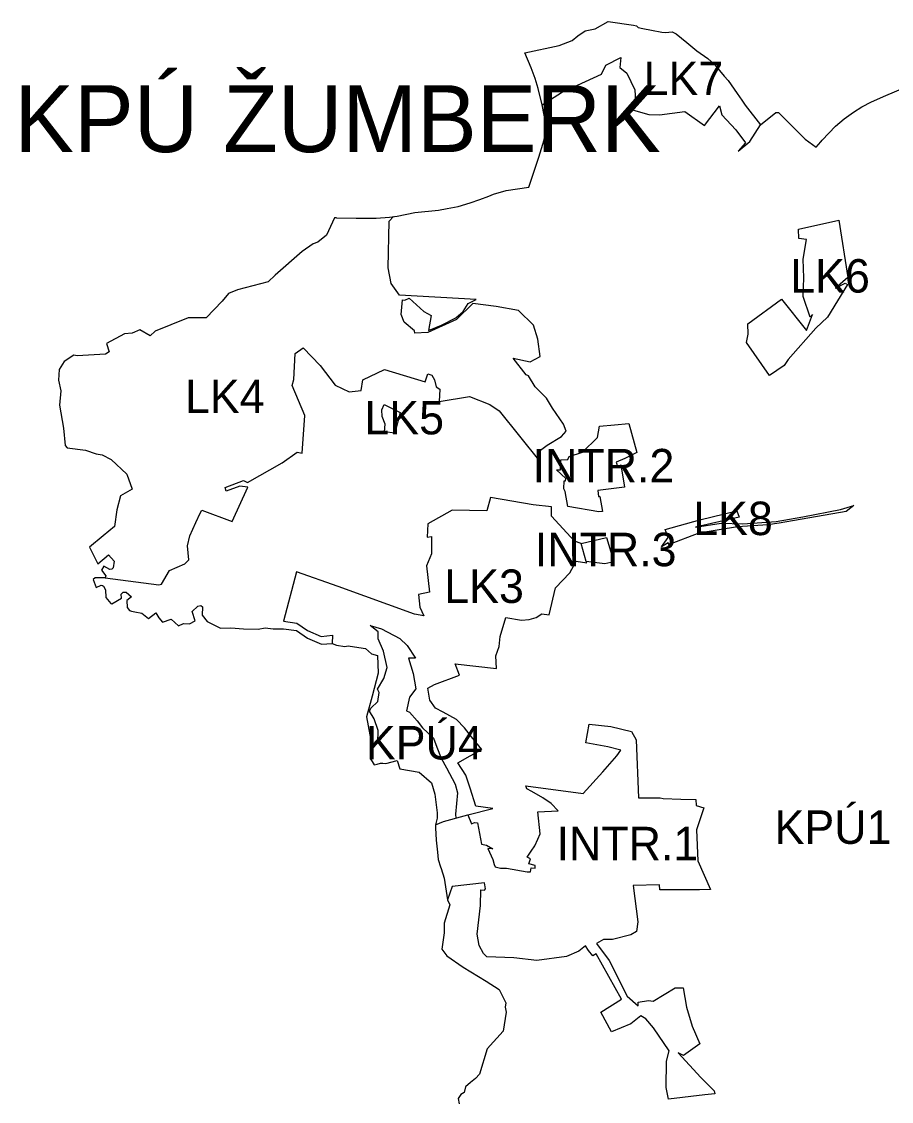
# Model space of a CAD drawing. Extents: x -744334 to -741989, y -1190045 to -1186328.
# Drawn here: x -744334 to -742775, y -1188264 to -1186328 of the extents above; entities that cross this region are included whole.
import ezdxf

# ---------------------------------------------------------------- set-up
doc = ezdxf.new("R2010")
doc.units = 0
for name, color, linetype in [('Hranice parcel', 7, 'Continuous'), ('Parcelní čísla', 7, 'Continuous'), ('Vnitřní kresba', 7, 'Continuous'), ('Značky budov', 7, 'Continuous')]:
    doc.layers.add(name, color=color, linetype=linetype)

msp = doc.modelspace()

# ---------------------------------------------------------------- linework, layer by layer
at = {"layer": 'Hranice parcel'}
msp.add_line((-743400.9, -1186477.3), (-743366.4, -1186455.4), dxfattribs=at)
for points in [[(-743366.4, -1186455.4), (-743294.4, -1186422.3), (-743286.6, -1186406.4), (-743259.8, -1186392.9), (-743261.7, -1186410.7), (-743248.9, -1186420.8), (-743234.9, -1186450.7), (-743233.5, -1186471.5), (-743237.3, -1186486.9), (-743209.9, -1186494.8), (-743190.7, -1186495.5), (-743145.5, -1186489.5), (-743109.8, -1186514.8), (-743083, -1186479.6), (-743079.1, -1186495.3), (-743054, -1186522.6), (-743036.7, -1186545.8), (-743049.3, -1186560.5), (-743028.9, -1186543), (-743009.5, -1186513.3)], [(-743867.4, -1187119.1), (-743840.2, -1187100), (-743831, -1187101.7), (-743826.3, -1187034.4), (-743849.4, -1186980.9), (-743846, -1186969.7), (-743844, -1186923.4), (-743829.7, -1186913.2), (-743798.7, -1186944.5), (-743771.8, -1186980.2), (-743747, -1186992.1), (-743725.6, -1186989.8), (-743722.5, -1186970.4), (-743683.7, -1186952), (-743610.6, -1186973.8), (-743605.8, -1186959.8), (-743598.7, -1186961.9), (-743593.9, -1186970.4), (-743591.2, -1186983.3), (-743584.7, -1186987), (-743585.4, -1187009.5), (-743531, -1187000.3), (-743494.6, -1187014.6), (-743478.2, -1187026.2), (-743405.1, -1187117.1), (-743408.5, -1187100.4), (-743392.2, -1187087.8), (-743366.3, -1187072.1), (-743357.8, -1187062.6), (-743362.9, -1187049.7), (-743382.3, -1187021.4), (-743393.5, -1187003.4), (-743413.3, -1186983.3), (-743425.5, -1186963.2), (-743429.6, -1186961.5), (-743452.7, -1186931.6), (-743422.5, -1186938.4), (-743404.8, -1186928.8), (-743408.5, -1186897.5), (-743416.3, -1186872.3), (-743443.5, -1186846.1), (-743483.7, -1186839), (-743525.5, -1186833.9), (-743554.8, -1186862.5), (-743605.8, -1186885.6), (-743629, -1186887), (-743629.6, -1186882.9), (-743648.3, -1186867.2), (-743653.8, -1186853.6), (-743651.1, -1186827.1), (-743647, -1186827.4), (-743639.5, -1186824.3), (-743613.3, -1186848.2), (-743599.7, -1186855.3), (-743604.8, -1186882.2), (-743581.7, -1186872.3), (-743555.8, -1186859.1), (-743542.9, -1186847.8), (-743533.4, -1186833.9), (-743519.4, -1186826.4), (-743656.5, -1186818.6), (-743671.6, -1186797.8), (-743677.2, -1186770), (-743675.1, -1186686.2), (-743667.7, -1186677.9)], [(-744011.3, -1187204.2), (-743956.9, -1187224.6), (-743928.7, -1187162.7), (-743943, -1187161), (-743967.5, -1187170.2), (-743969.2, -1187163.7), (-743936.5, -1187151.1), (-743929.3, -1187154.5), (-743867.4, -1187119.1)], [(-743330.9, -1187263.8), (-743343.2, -1187259.8), (-743384, -1187214.7), (-743384.3, -1187198), (-743417, -1187194.3), (-743493.9, -1187181.6), (-743500.1, -1187205.4), (-743562.2, -1187204.2), (-743605.7, -1187228.6), (-743606.9, -1187252.3), (-743599.2, -1187251.1), (-743599.2, -1187282.6), (-743608.5, -1187303.9), (-743602.9, -1187350.9), (-743622.4, -1187355.2), (-743620.5, -1187377.8), (-743613.4, -1187393.5), (-743629.8, -1187390.4)], [(-744184.6, -1187325.6), (-744088.2, -1187338), (-744083.5, -1187336.6), (-744069.2, -1187312.1), (-744055.2, -1187306.3), (-744041.6, -1187300.5), (-744034.5, -1187293), (-744036.9, -1187267.9), (-744032.4, -1187249.8), (-744021.9, -1187226.3), (-744014.4, -1187209.3), (-744011.3, -1187204.2)], [(-743606.2, -1187523.1), (-743594.3, -1187516.5), (-743549.2, -1187499.8), (-743556.9, -1187479.7), (-743483.1, -1187487.8), (-743484, -1187465.2), (-743477.9, -1187448.2), (-743476, -1187430.3), (-743466.1, -1187396.3), (-743438.3, -1187401), (-743424.1, -1187400), (-743411.8, -1187396.6), (-743401.3, -1187389.8), (-743388.6, -1187391.4), (-743376.9, -1187343.2), (-743351.6, -1187316.3), (-743340.1, -1187295.6), (-743321, -1187298.7), (-743322.2, -1187296.3)], [(-743629.8, -1187390.4), (-743766.8, -1187340.8), (-743841.5, -1187314.6), (-743864.8, -1187402.9)], [(-743864.8, -1187402.9), (-743840.7, -1187406.8), (-743821.7, -1187419.9), (-743797, -1187430.8), (-743777, -1187428.2), (-743777.3, -1187443)], [(-743705.5, -1187631.7), (-743695.5, -1187621.3), (-743694.9, -1187599.1), (-743702, -1187578.1), (-743710.4, -1187564.2), (-743707.9, -1187559.2), (-743695.5, -1187546.9), (-743693.1, -1187530.8), (-743696.2, -1187524.7), (-743684.8, -1187505.8), (-743678.6, -1187486.1), (-743685.4, -1187457.1), (-743695.2, -1187434.9), (-743695.2, -1187421.9), (-743709.1, -1187410.5), (-743689.1, -1187417), (-743656.4, -1187434.2), (-743643.1, -1187446.6), (-743628, -1187469.1), (-743640.9, -1187469.4), (-743632, -1187496.9), (-743627.7, -1187524.4), (-743639.1, -1187539.5), (-743644.3, -1187563.9), (-743639.1, -1187566.3), (-743624.9, -1187581.5), (-743615.6, -1187594.1), (-743595.6, -1187612.9), (-743589.7, -1187629), (-743582.3, -1187648.4), (-743572.5, -1187665.7), (-743557, -1187695), (-743553, -1187710.8), (-743556.4, -1187749.1), (-743556, -1187756.2)], [(-743534.1, -1187750), (-743489.5, -1187739.1), (-743520.2, -1187734.4), (-743529.8, -1187702.2), (-743537.8, -1187679.2), (-743552.2, -1187657.1), (-743529.8, -1187644.2), (-743509, -1187633.2), (-743527.7, -1187610.1), (-743540.4, -1187594.4), (-743554.3, -1187579.1), (-743578.5, -1187566.4), (-743592, -1187559), (-743602.2, -1187544.5), (-743606.2, -1187523.1)]]:
    msp.add_lwpolyline(points, dxfattribs=at)
for points in [[(-742869.2, -1186684.4), (-742853, -1186787), (-742875.3, -1186806.1), (-742857.9, -1186797.1), (-742853.8, -1186799.6), (-742889.5, -1186858.4), (-742910.6, -1186877.8), (-742960, -1186933.8), (-742967.3, -1186944.7), (-742993.2, -1186962.6), (-743034.6, -1186903.8), (-743031.7, -1186888.8), (-743032.1, -1186870.1), (-742972.2, -1186825.9), (-742927.2, -1186882.3), (-742916.3, -1186853.5), (-742920.3, -1186858), (-742933.3, -1186821.1), (-742932.1, -1186787.8), (-742933.3, -1186754.2), (-742927.2, -1186718.9), (-742941, -1186716.9), (-742941.4, -1186700.2)], [(-743655.6, -1187029.2), (-743665.1, -1187066), (-743683.5, -1187063.4), (-743682.2, -1187050), (-743688.1, -1187036), (-743688.3, -1187024.5), (-743684.2, -1187014.8)], [(-743180.4, -1187238.7), (-743118.5, -1187221.5), (-743051.9, -1187205.4), (-743047.7, -1187216.8), (-743126.3, -1187234.8), (-743080, -1187227.5), (-743041.5, -1187228.3), (-742981.7, -1187224.1), (-742933.8, -1187216.3), (-742866.2, -1187202.8), (-742842.2, -1187195.8), (-742856, -1187206.7), (-742975.9, -1187227.3), (-742996.7, -1187230.4), (-743050.6, -1187234), (-743120.3, -1187245.2), (-743173.4, -1187265.5), (-743175.3, -1187262.8), (-743186.9, -1187269.6), (-743175.2, -1187252.9)]]:
    msp.add_lwpolyline(points, close=True, dxfattribs=at)
at = {"layer": 'Parcelní čísla'}
for p, q in [((-743337.2, -1186353.8), (-743323.8, -1186344.8)), ((-743323.8, -1186344.8), (-743306.1, -1186341.6)), ((-743306.1, -1186341.6), (-743282.4, -1186328.4)), ((-743282.4, -1186328.4), (-743237.2, -1186334.6)), ((-743237.2, -1186334.6), (-743232.1, -1186336.2)), ((-743232.1, -1186336.2), (-743228.6, -1186338.7)), ((-743228.6, -1186338.7), (-743220.8, -1186340.9)), ((-743220.8, -1186340.9), (-743204.8, -1186343.9)), ((-743204.8, -1186343.9), (-743186.3, -1186347.3)), ((-743370.6, -1186371.1), (-743347.3, -1186362.5)), ((-743347.3, -1186362.5), (-743337.2, -1186353.8)), ((-743186.3, -1186347.3), (-743179.9, -1186347.7)), ((-743179.9, -1186347.7), (-743167.8, -1186346.8)), ((-743167.8, -1186346.8), (-743160.6, -1186350.3)), ((-743160.6, -1186350.3), (-743141.7, -1186365.6)), ((-743432.2, -1186384.6), (-743370.6, -1186371.1)), ((-743141.7, -1186365.6), (-743123.4, -1186380.8)), ((-743123.4, -1186380.8), (-743104.2, -1186394.4)), ((-743420.5, -1186411), (-743432.2, -1186384.6)), ((-743104.2, -1186394.4), (-743091.7, -1186406.1)), ((-743413.8, -1186430.3), (-743420.5, -1186411)), ((-743091.7, -1186406.1), (-743074.6, -1186426)), ((-743408, -1186448.5), (-743413.8, -1186430.3)), ((-743074.6, -1186426), (-743067.6, -1186434.2)), ((-743067.6, -1186434.2), (-743051.2, -1186457.4)), ((-743400.9, -1186477.3), (-743408, -1186448.5)), ((-743051.2, -1186457.4), (-743043.1, -1186469.4)), ((-742810.5, -1186472), (-742784.7, -1186460.7)), ((-742784.7, -1186460.7), (-742749.7, -1186445.8)), ((-743397.4, -1186495.9), (-743400.9, -1186477.3)), ((-743043.1, -1186469.4), (-743036.9, -1186478.1)), ((-743036.9, -1186478.1), (-743009.5, -1186513.3)), ((-742827.8, -1186481.3), (-742810.5, -1186472)), ((-743395.2, -1186510.1), (-743397.4, -1186495.9)), ((-743009.5, -1186513.3), (-742982.2, -1186491.2)), ((-742982.2, -1186491.2), (-742977.4, -1186491.2)), ((-742977.4, -1186491.2), (-742949.4, -1186519.5)), ((-742859.6, -1186502.8), (-742842.9, -1186490.9)), ((-742842.9, -1186490.9), (-742827.8, -1186481.3)), ((-743394.4, -1186521), (-743395.2, -1186510.1)), ((-742898.8, -1186541), (-742874.8, -1186515.5)), ((-742874.8, -1186515.5), (-742859.6, -1186502.8)), ((-743397.4, -1186540), (-743394.4, -1186521)), ((-742949.4, -1186519.5), (-742929.7, -1186538.8)), ((-743406.7, -1186571.2), (-743397.4, -1186540)), ((-742929.7, -1186538.8), (-742910, -1186553.7)), ((-742910, -1186553.7), (-742901.3, -1186543.7)), ((-742901.3, -1186543.7), (-742898.8, -1186541)), ((-743424.8, -1186625.1), (-743406.7, -1186571.2)), ((-743488.3, -1186637.7), (-743465.4, -1186630.9)), ((-743465.4, -1186630.9), (-743424.8, -1186625.1)), ((-743551.5, -1186660), (-743530.2, -1186653.4)), ((-743530.2, -1186653.4), (-743512.5, -1186647.5)), ((-743512.5, -1186647.5), (-743496.5, -1186641)), ((-743496.5, -1186641), (-743488.3, -1186637.7)), ((-743660.9, -1186677.2), (-743629.5, -1186670.8)), ((-743629.5, -1186670.8), (-743586.7, -1186666.2)), ((-743586.7, -1186666.2), (-743571.4, -1186663.2)), ((-743571.4, -1186663.2), (-743551.5, -1186660)), ((-743773.2, -1186680.1), (-743787.7, -1186711.1)), ((-743769.7, -1186680), (-743773.2, -1186680.1)), ((-743769.7, -1186680), (-743734.5, -1186680.9)), ((-743734.5, -1186680.9), (-743698.8, -1186680.9)), ((-743698.8, -1186680.9), (-743674.5, -1186678.6)), ((-743674.5, -1186678.6), (-743660.9, -1186677.2)), ((-743787.7, -1186711.1), (-743803.2, -1186723.9)), ((-743811.3, -1186726.6), (-743831.4, -1186740.7)), ((-743803.2, -1186723.9), (-743811.3, -1186726.6)), ((-743831.4, -1186740.7), (-743879.6, -1186782.6)), ((-743879.6, -1186782.6), (-743892.3, -1186794.8)), ((-743947.3, -1186809.1), (-743963.5, -1186815.8)), ((-743892.3, -1186794.8), (-743947.3, -1186809.1)), ((-743963.5, -1186815.8), (-743974.5, -1186829.5)), ((-743974.5, -1186829.5), (-744003.5, -1186859.6)), ((-744035.9, -1186859.3), (-744066.5, -1186872)), ((-744003.5, -1186859.6), (-744035.9, -1186859.3)), ((-744122, -1186880.9), (-744135.8, -1186886.9)), ((-744103.7, -1186891.4), (-744122, -1186880.9)), ((-744094.6, -1186883), (-744103.7, -1186891.4)), ((-744066.5, -1186872), (-744094.6, -1186883)), ((-744149.6, -1186887.9), (-744181.9, -1186905.5)), ((-744181.9, -1186905.5), (-744177.4, -1186920.5)), ((-744135.8, -1186886.9), (-744149.6, -1186887.9)), ((-744183.8, -1186924.2), (-744234.7, -1186927.3)), ((-744177.4, -1186920.5), (-744183.8, -1186924.2)), ((-744258, -1186937.7), (-744267, -1186952)), ((-744240.5, -1186926.3), (-744258, -1186937.7)), ((-744234.7, -1186927.3), (-744240.5, -1186926.3)), ((-744267, -1186952), (-744268, -1186970.9)), ((-744268, -1186970.9), (-744263.7, -1186990.2)), ((-744263.7, -1186990.2), (-744266.2, -1187015.9)), ((-744266.2, -1187015.9), (-744258.9, -1187056.9)), ((-744258.9, -1187056.9), (-744255.9, -1187088.1)), ((-744255.9, -1187088.1), (-744252.7, -1187092.5)), ((-744252.7, -1187092.5), (-744219.9, -1187096.7)), ((-744219.9, -1187096.7), (-744200.5, -1187103.2)), ((-744200.5, -1187103.2), (-744189.8, -1187105.1)), ((-744189.8, -1187105.1), (-744173.9, -1187113.1)), ((-744173.9, -1187113.1), (-744145.4, -1187139.6)), ((-744145.4, -1187139.6), (-744135.9, -1187166.5)), ((-744135.9, -1187166.5), (-744157.1, -1187178.5)), ((-744157.1, -1187178.5), (-744163.5, -1187203.3)), ((-744163.5, -1187203.3), (-744167.7, -1187233.4)), ((-744167.7, -1187233.4), (-744188, -1187250.2)), ((-744188, -1187250.2), (-744212.5, -1187270.3)), ((-744212.5, -1187270.3), (-744197.4, -1187300.2)), ((-744197.4, -1187300.2), (-744178.5, -1187283.9)), ((-744178.5, -1187283.9), (-744168.1, -1187295.3)), ((-744186.7, -1187304.6), (-744190.8, -1187311.9)), ((-744190.8, -1187311.9), (-744183.1, -1187321.6)), ((-744176.3, -1187310.2), (-744186.7, -1187304.6)), ((-744172.5, -1187309.6), (-744176.3, -1187310.2)), ((-744170.3, -1187307.5), (-744172.5, -1187309.6)), ((-744168.1, -1187295.3), (-744170.3, -1187307.5)), ((-744205.9, -1187328.5), (-744200.6, -1187342.4)), ((-744183.1, -1187321.6), (-744184.6, -1187325.6)), ((-744189.4, -1187339.4), (-744187.3, -1187340.3)), ((-744187.3, -1187340.3), (-744184.1, -1187347)), ((-744184.1, -1187347), (-744183.5, -1187360.8)), ((-744155.8, -1187354.6), (-744152.3, -1187351.1)), ((-744152.3, -1187351.1), (-744146.8, -1187351.3)), ((-744146.8, -1187351.3), (-744137.2, -1187359.4)), ((-744183.5, -1187360.8), (-744174.5, -1187371.5)), ((-744155, -1187362), (-744155.8, -1187354.6)), ((-744137.2, -1187359.4), (-744145.4, -1187366)), ((-744145.4, -1187366), (-744145.2, -1187378.4)), ((-744137, -1187384.9), (-744131.3, -1187386.4)), ((-744131.3, -1187386.4), (-744118.9, -1187388.5)), ((-744118.9, -1187388.5), (-744106.5, -1187398.2)), ((-744106.5, -1187398.2), (-744093.3, -1187387.9)), ((-744093.3, -1187387.9), (-744088, -1187397.1)), ((-744028.5, -1187385.6), (-744018.3, -1187375.9)), ((-744023.3, -1187402.3), (-744028.5, -1187385.6)), ((-744018.3, -1187375.9), (-744012.8, -1187374.9)), ((-744012.8, -1187374.9), (-744009.7, -1187377.2)), ((-744009.7, -1187377.2), (-744010.5, -1187392.1)), ((-744088, -1187397.1), (-744081.5, -1187404.6)), ((-744081.5, -1187404.6), (-744066.2, -1187399.6)), ((-744066.2, -1187399.6), (-744053.2, -1187411.2)), ((-744053.2, -1187411.2), (-744044.2, -1187407)), ((-744044.2, -1187407), (-744033, -1187407.7)), ((-744033, -1187407.7), (-744023.3, -1187402.3)), ((-744010.5, -1187392.1), (-744001.8, -1187403.5)), ((-744001.8, -1187403.5), (-743977.7, -1187415.3)), ((-743977.7, -1187415.3), (-743958.9, -1187415.1)), ((-743958.9, -1187415.1), (-743936.7, -1187417)), ((-743936.7, -1187417), (-743910.2, -1187417.6)), ((-743910.2, -1187417.6), (-743897.4, -1187414.7)), ((-743897.4, -1187414.7), (-743883.2, -1187416.6)), ((-743883.2, -1187416.6), (-743864.5, -1187416.5)), ((-743864.5, -1187416.5), (-743841.5, -1187419.8)), ((-743841.5, -1187419.8), (-743821.8, -1187433.6)), ((-743821.8, -1187433.6), (-743796.7, -1187444.5)), ((-743796.7, -1187444.5), (-743777.3, -1187443)), ((-743777.3, -1187443), (-743769.6, -1187446.2)), ((-743769.6, -1187446.2), (-743754.6, -1187448.4)), ((-743754.6, -1187448.4), (-743748.5, -1187447.5)), ((-743748.5, -1187447.5), (-743729.9, -1187450.2)), ((-743729.9, -1187450.2), (-743717.6, -1187452.1)), ((-743717.6, -1187452.1), (-743707.2, -1187461.5)), ((-743707.2, -1187461.5), (-743696.3, -1187464.8)), ((-743696.3, -1187464.8), (-743695.1, -1187496.4)), ((-743695.1, -1187496.4), (-743705.5, -1187537.6)), ((-743705.5, -1187537.6), (-743716.2, -1187574.7)), ((-743716.2, -1187574.7), (-743707.2, -1187623.2)), ((-743705.7, -1187632.6), (-743709, -1187650.9)), ((-743707.2, -1187623.2), (-743707.2, -1187630.4)), ((-743707.2, -1187630.4), (-743705.4, -1187630.8)), ((-743705.4, -1187630.8), (-743705.7, -1187632.6)), ((-743709, -1187650.9), (-743707.5, -1187651.5)), ((-743707.5, -1187651.5), (-743701.9, -1187660.6)), ((-743701.9, -1187660.6), (-743697, -1187659.4)), ((-743697, -1187659.4), (-743691.1, -1187657.3)), ((-743691.1, -1187657.3), (-743686.4, -1187657.8)), ((-743686.4, -1187657.8), (-743681.3, -1187658.4)), ((-743681.3, -1187658.4), (-743660.8, -1187652.9)), ((-743660.8, -1187652.9), (-743656.4, -1187667.6)), ((-743656.4, -1187667.6), (-743621.4, -1187673.6)), ((-743621.4, -1187673.6), (-743599.6, -1187692.7)), ((-743599.6, -1187692.7), (-743593.4, -1187713.2)), ((-743593.4, -1187713.2), (-743589.1, -1187746.8)), ((-743589.5, -1187756.4), (-743592.2, -1187767.9)), ((-743589.1, -1187746.8), (-743589.5, -1187756.4)), ((-743592.2, -1187769.6), (-743592.3, -1187773.7)), ((-743592.3, -1187773.7), (-743590.9, -1187795.7)), ((-743592.2, -1187767.9), (-743592.2, -1187769.6)), ((-743590.9, -1187795.7), (-743588.6, -1187817)), ((-743588.6, -1187817), (-743587.3, -1187830.2)), ((-743587.3, -1187830.2), (-743583.2, -1187843.4)), ((-743583.2, -1187843.4), (-743582.2, -1187846.3)), ((-743582.2, -1187846.3), (-743576.8, -1187863.7)), ((-743576.8, -1187863.7), (-743570.6, -1187902.6)), ((-743566.8, -1187911.2), (-743576.9, -1187944.5)), ((-743570.6, -1187902.6), (-743566.8, -1187911.2)), ((-743576.9, -1187944.5), (-743576.8, -1187961.4)), ((-743576.8, -1187961.4), (-743580.8, -1187990.8)), ((-743580.8, -1187990.8), (-743572.1, -1188003)), ((-743572.1, -1188003), (-743542.7, -1188023.2)), ((-743542.7, -1188023.2), (-743501.1, -1188048.5)), ((-743501.1, -1188048.5), (-743478.2, -1188063.1)), ((-743478.2, -1188063.1), (-743466, -1188087.4)), ((-743466, -1188087.4), (-743467.5, -1188095.2)), ((-743470.7, -1188137.7), (-743499.7, -1188169.4)), ((-743499.7, -1188169.4), (-743513.6, -1188215)), ((-743513.6, -1188215), (-743520.7, -1188222.6)), ((-743538.5, -1188237.7), (-743540.7, -1188247.7)), ((-743529.7, -1188230.2), (-743538.5, -1188237.7)), ((-743520.7, -1188222.6), (-743529.7, -1188230.2)), ((-743546.6, -1188251.4), (-743551.5, -1188258.5)), ((-743551.5, -1188258.5), (-743549.5, -1188268)), ((-743540.7, -1188247.7), (-743546.6, -1188251.4))]:
    msp.add_line(p, q, dxfattribs=at)
for points in [[(-744184.6, -1187325.6), (-744202.4, -1187325.2), (-744205.9, -1187328.5)], [(-744200.6, -1187342.4), (-744191.5, -1187338.5), (-744189.4, -1187339.4)], [(-744174.5, -1187371.5), (-744172.7, -1187371.9), (-744155, -1187362)], [(-744145.2, -1187378.4), (-744141.1, -1187384), (-744137, -1187384.9)], [(-743467.5, -1188095.2), (-743465.3, -1188103.6), (-743470.7, -1188137.7)]]:
    msp.add_lwpolyline(points, dxfattribs=at)
at = {"layer": 'Vnitřní kresba'}
for points in [[(-743259.9, -1187122.9), (-743253.3, -1187162.8), (-743300.9, -1187168.9), (-743299.7, -1187179.8), (-743297.8, -1187179.8), (-743292.7, -1187206.7), (-743299.2, -1187206.9), (-743354.9, -1187197.5), (-743359.8, -1187170.7), (-743361.9, -1187165.6), (-743361.8, -1187151.2), (-743358.9, -1187151.5), (-743358.6, -1187147.2), (-743375.2, -1187132), (-743368.3, -1187131.6), (-743367.4, -1187113.6), (-743355.1, -1187113.1), (-743352.8, -1187108), (-743328.4, -1187100.4), (-743301.5, -1187073.7), (-743298.2, -1187053.4), (-743271.3, -1187051.1), (-743245.7, -1187049), (-743231.4, -1187100.9), (-743252.9, -1187111.7), (-743268.2, -1187117.9), (-743265.4, -1187127.4)], [(-743272.7, -1187296.6), (-743288.6, -1187300), (-743322.2, -1187296.3), (-743330.9, -1187263.8), (-743285.5, -1187253.1)]]:
    msp.add_lwpolyline(points, close=True, dxfattribs=at)
for points in [[(-743592.2, -1187767.9), (-743577.9, -1187762.3), (-743534.1, -1187750), (-743527.7, -1187766.4), (-743522.5, -1187763.7), (-743517.1, -1187764.5), (-743510, -1187802.5), (-743500.6, -1187804.7), (-743489.5, -1187811.4), (-743498.6, -1187810.3), (-743489.7, -1187830.1), (-743487.1, -1187839.1), (-743485.3, -1187843.1), (-743475.5, -1187846), (-743464.8, -1187846), (-743427.8, -1187852.2), (-743421.6, -1187852.4), (-743420.9, -1187845.1), (-743413.3, -1187845.5), (-743413.6, -1187841.1), (-743424.7, -1187838.2), (-743422, -1187828.8), (-743427.8, -1187826.3), (-743420.7, -1187815), (-743414.4, -1187805.6), (-743408.9, -1187793.8), (-743404.4, -1187784.2), (-743408.7, -1187744.8), (-743372.4, -1187743), (-743384.6, -1187730.1), (-743400, -1187719.8), (-743419.6, -1187708.5), (-743428.3, -1187703.6), (-743430.3, -1187698.2), (-743327.4, -1187711.8), (-743292.4, -1187672.8), (-743267.2, -1187644.7), (-743259.9, -1187634.3), (-743283.5, -1187628.2), (-743322.5, -1187621.3), (-743316.9, -1187587.9), (-743278.1, -1187591.9), (-743240.7, -1187600.8), (-743232.7, -1187616), (-743228.2, -1187719.4), (-743189.5, -1187719.4), (-743184.1, -1187720.9), (-743152.5, -1187722.3), (-743125.6, -1187722.9), (-743124.7, -1187733.2), (-743111.3, -1187737.9), (-743124, -1187777.1), (-743121.8, -1187832.9), (-743099.2, -1187884), (-743119.1, -1187884.4), (-743190.1, -1187884.4), (-743190.4, -1187875.8), (-743238, -1187877), (-743229.4, -1187942.1), (-743231.9, -1187959.1), (-743241.8, -1187965.3), (-743274.7, -1187973.9), (-743290.8, -1187973.5), (-743303.8, -1187980.9), (-743280.6, -1188011), (-743248.7, -1188074.9), (-743229, -1188092.3), (-743229, -1188085.7), (-743210.1, -1188082.9), (-743202.1, -1188084.1), (-743162.3, -1188060.1), (-743147.9, -1188060.3), (-743142.3, -1188095.1), (-743132.3, -1188129.2), (-743118.5, -1188160.6), (-743147.4, -1188181.6), (-743157.1, -1188176.5), (-743116.7, -1188220.7), (-743092.7, -1188244.8), (-743091.4, -1188250.4)], [(-743091.4, -1188250.4), (-743109.5, -1188251.8), (-743174.2, -1188259.6), (-743178.6, -1188238.7), (-743178.1, -1188191.6), (-743173, -1188172.9), (-743201.5, -1188132.2), (-743214.9, -1188116), (-743224.3, -1188110.7), (-743242.2, -1188124.6), (-743276.5, -1188139.1), (-743296, -1188103.7), (-743258.9, -1188080.6), (-743304.1, -1187999.4), (-743309.9, -1188003), (-743318, -1187993.6), (-743323, -1187984.9), (-743335.5, -1187994.4), (-743357.6, -1188004.2), (-743410.5, -1188011.4), (-743451.5, -1188006.4), (-743500, -1188004.4), (-743505.9, -1187998.9), (-743513.7, -1187984.4), (-743517.6, -1187964), (-743511.7, -1187912.4), (-743511.2, -1187884.5), (-743504.2, -1187885.4), (-743502.6, -1187883), (-743504.2, -1187872.3), (-743562.6, -1187878.9), (-743570.6, -1187902.6)]]:
    msp.add_lwpolyline(points, dxfattribs=at)

# ---------------------------------------------------------------- texts
at = {"layer": 'Značky budov'}
for s, height, p in [('LK7', 60, (-743219.1, -1186460.2)), ('KPÚ ŽUMBERK', 120, (-744347.4, -1186562.3)), ('LK6', 60, (-742956.2, -1186814.1)), ('LK4', 60, (-744041.3, -1187030.2)), ('LK5', 60, (-743719.7, -1187068.2)), ('INTR.2', 60, (-743418.1, -1187154.3)), ('LK8', 60, (-743130.2, -1187248.8)), ('INTR.3', 60, (-743414.2, -1187304.5)), ('LK3', 60, (-743576.5, -1187370.4)), ('KPÚ4', 60, (-743717.1, -1187650.9)), ('KPÚ1', 60, (-742984.4, -1187802.2)), ('INTR.1', 60, (-743375.2, -1187831.6))]:
    msp.add_text(s, height=height, dxfattribs=at).set_placement(p)

doc.saveas('drawing.dxf')
